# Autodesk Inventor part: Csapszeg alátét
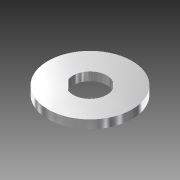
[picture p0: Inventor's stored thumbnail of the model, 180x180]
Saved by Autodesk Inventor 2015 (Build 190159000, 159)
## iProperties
Created: 2013-02
Part Number: Csapszeg alátét
Material: Generic
Document SubType Name: Modeling
Designer: Marci
Density: 1 g/cm^3
Appearance: Chrome - Polished
Author: Marci
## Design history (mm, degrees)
sketch "Sketch1"
  geometry: C1 r 4 at (0, 0); C2 r 10 at (0, 0); 1 further point
  constraints: 2 centre point, 2 coincident
  dimensions: "d0" = 8 diameter of C1; "d1" = 20 diameter of C2
extrude "Extrusion1" new body sketch "Sketch1" distance "d2" = 2; taper "d3" = 0 deg
body "Solid1"
